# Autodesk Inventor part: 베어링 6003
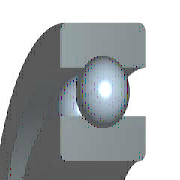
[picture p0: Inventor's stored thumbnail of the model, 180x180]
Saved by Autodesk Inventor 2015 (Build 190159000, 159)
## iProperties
IsCustomPart: 1
Company: 한국ATC센터
Created: 2014-07
Part Number: 베어링 6003
Material: 강, 연강
Description: 깊은 그루브 볼 베어링
Document SubType Name: Modeling
Standard: KS B 2023
Designer: KYOUNG IL JANG
Standards Organization: KS
Language: ko-KR
Size Designation: 6003 - 17 x 35 x 10
Categories: <MemberInstance><Categories><Category DisplayName="샤프트 부품" InternalName="7f7aeb1f-a693-4053-b835-cee3144e0d98" Mnemonic="SHFT"><Category DisplayName="베어링" Inter
Density: 1 g/cm^3
Appearance: 강철
Author: KYOUNG IL JANG
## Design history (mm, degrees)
sketch "스케치" dims "d0" = 4.68 (= -0.26 x WD + 0.26 x BD)
  geometry: L1 (2.66, 13)-(7.34, 13); L2 (5, 13)-(5, 10.66); L3 (5, 13)-(5, 15.34); L4 (3.261, 11.434)-(0, 11.434); L5 (0, 8.5)-(10, 8.5); L6 (3.261, 14.566)-(0, 14.566); L7 (0, 17.5)-(10, 17.5); L8 (10, 8.5)-(10, 11.434); L9 (6.739, 11.434)-(10, 11.434); L10 (6.739, 14.566)-(10, 14.566); L11 (10, 17.5)-(10, 14.566); L12 (-1.4, 0)-(8.4, 0) reference; L13 (0, -0.3)-(0, 5.3) reference
  constraints: 22 end point, 4 point on line, 2 collinear, 2 perpendicular, 2 symmetric about line, 1 midpoint, 1 parallel, 14 other
  dimensions: "d9" = 17 diameter of L5 L12 (= WD); "d11" = 35 diameter of L7 L12 (= BD); "d12" = 10 distance between parallel lines of L8 L13 (= KB); "d13" = 22.868 diameter of L9 L12 (= 0.326 x BD + 0.674 x WD)
revolve "본체" stored, may be unused: angle "d6" = 90 deg
revolve "볼" stored, may be unused: angle "d7" = 90 deg
pattern_circular "IDS_ARRAYBALL[SIMPL:T]" dims angle "d3" = 360 deg
body "Solid1"
fillet "모깎기1" dims "d1" = 0.3 (= KRS)
other parameters: "WD" = 17 [user parameter; used in 5 equation terms], "BD" = 35 [user parameter; used in 5 equation terms], "KB" = 10 [user parameter; used in 1 equation term], "KRS" = 0.3 [user parameter; used in 1 equation term], "d4" = 0, "d5" = 0, "d8" = 0, "d14" = 0, "d15" = 0, "BBA" = 0 [user parameter], "BC0" = 3250000 [user parameter], "BC" = 6050000 [user parameter], "BR" = 17.5 (= 0.5 x BD) [user parameter], "WR" = 8.5 (= 0.5 x WD) [user parameter]
